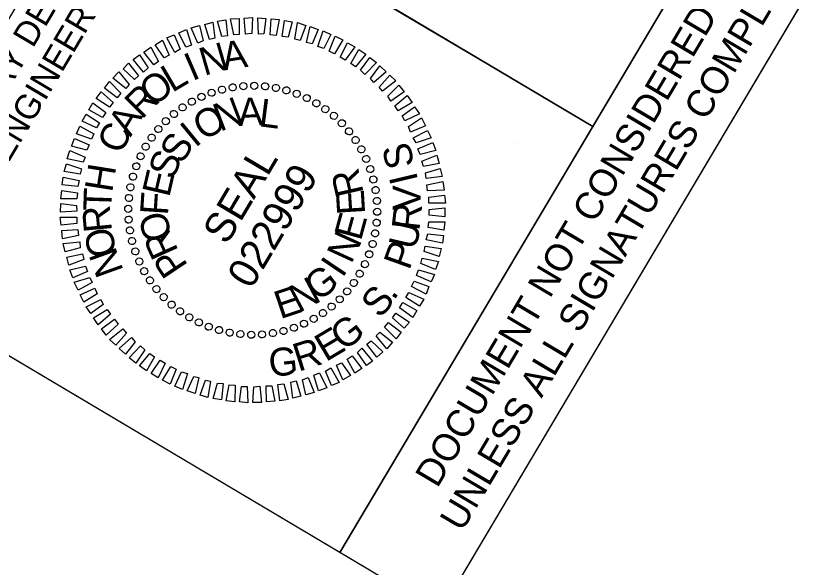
# Model space of a CAD drawing. Extents: x 2137081 to 2142019, y 404041 to 411238.
# Drawn here: x 2141049.2 to 2141211.9, y 410763.2 to 410874.6 of the extents above; entities that cross this region are included whole.
import ezdxf

# ---------------------------------------------------------------- set-up
doc = ezdxf.new("R2010")
doc.units = 0
for name, color, linetype in [('Prop Guardrail', 7, 'Continuous'), ('Sheet Clip Boundary CELL', 7, 'Continuous'), ('Sheet Plan And Profile CELL', 7, 'Continuous'), ('Sheet Sticker Exception Certification CELL', 7, 'Continuous')]:
    doc.layers.add(name, color=color, linetype=linetype)

msp = doc.modelspace()

# ---------------------------------------------------------------- linework, layer by layer
at = {"layer": 'Prop Guardrail'}
for p, q in [((2141095.05, 410860.53), (2141095.05, 410860.53)), ((2141097.3, 410860.59), (2141097.3, 410860.59)), ((2141088.66, 410859.19), (2141088.66, 410859.19)), ((2141090.77, 410859.81), (2141090.77, 410859.81)), ((2141092.92, 410860.28), (2141092.92, 410860.28)), ((2141099.45, 410860.48), (2141099.45, 410860.48)), ((2141101.6, 410860.19), (2141101.6, 410860.19)), ((2141103.75, 410859.68), (2141103.75, 410859.68)), ((2141105.87, 410858.94), (2141105.87, 410858.94)), ((2141084.67, 410857.37), (2141084.67, 410857.37)), ((2141086.65, 410858.35), (2141086.65, 410858.35)), ((2141107.83, 410858.13), (2141107.83, 410858.13)), ((2141082.81, 410856.2), (2141082.81, 410856.2)), ((2141109.78, 410857.09), (2141109.78, 410857.09)), ((2141111.63, 410855.88), (2141111.63, 410855.88)), ((2141081.01, 410854.94), (2141081.01, 410854.94)), ((2141113.37, 410854.49), (2141113.37, 410854.49)), ((2141079.42, 410853.44), (2141079.42, 410853.44)), ((2141114.95, 410853.03), (2141114.95, 410853.03)), ((2141077.89, 410851.84), (2141077.89, 410851.84)), ((2141116.42, 410851.4), (2141116.42, 410851.4)), ((2141076.53, 410850.14), (2141076.53, 410850.14)), ((2141117.71, 410849.64), (2141117.71, 410849.64)), ((2141075.32, 410848.3), (2141075.32, 410848.3)), ((2141118.92, 410847.76), (2141118.92, 410847.76)), ((2141150.48, 410848.89), (2141150.48, 410848.89)), ((2141074.28, 410846.35), (2141074.28, 410846.35)), ((2141073.44, 410844.34), (2141073.44, 410844.34)), ((2141119.86, 410845.8), (2141119.86, 410845.8)), ((2141120.75, 410843.76), (2141120.75, 410843.76)), ((2141072.77, 410842.23), (2141072.77, 410842.23)), ((2141121.36, 410841.65), (2141121.36, 410841.65)), ((2141072.21, 410840.12), (2141072.21, 410840.12)), ((2141121.83, 410839.5), (2141121.83, 410839.5)), ((2141071.96, 410837.94), (2141071.96, 410837.94)), ((2141122.06, 410837.33), (2141122.06, 410837.33)), ((2141071.83, 410835.74), (2141071.83, 410835.74)), ((2141096.94, 410835.46), (2141096.94, 410835.46)), ((2141122.15, 410835.12), (2141122.15, 410835.12)), ((2141071.92, 410833.54), (2141071.92, 410833.54)), ((2141122.01, 410832.93), (2141122.01, 410832.93)), ((2141072.14, 410831.36), (2141072.14, 410831.36)), ((2141121.68, 410830.8), (2141121.68, 410830.8)), ((2141072.62, 410829.22), (2141072.62, 410829.22)), ((2141121.21, 410828.63), (2141121.21, 410828.63)), ((2141073.23, 410827.11), (2141073.23, 410827.11)), ((2141120.45, 410826.58), (2141120.45, 410826.58)), ((2141074.03, 410825.12), (2141074.03, 410825.12)), ((2141075.05, 410823.11), (2141075.05, 410823.11)), ((2141119.61, 410824.57), (2141119.61, 410824.57)), ((2141118.57, 410822.62), (2141118.57, 410822.62)), ((2141076.18, 410821.28), (2141076.18, 410821.28)), ((2141117.36, 410820.78), (2141117.36, 410820.78)), ((2141077.46, 410819.52), (2141077.46, 410819.52)), ((2141116, 410819.08), (2141116, 410819.08)), ((2141078.94, 410817.89), (2141078.94, 410817.89)), ((2141114.56, 410817.43), (2141114.56, 410817.43)), ((2141080.61, 410816.38), (2141080.61, 410816.38)), ((2141082.26, 410815.04), (2141082.26, 410815.04)), ((2141112.88, 410815.98), (2141112.88, 410815.98)), ((2141084.11, 410813.83), (2141084.11, 410813.83)), ((2141109.31, 410813.5), (2141109.31, 410813.5)), ((2141111.17, 410814.67), (2141111.17, 410814.67)), ((2141086.05, 410812.79), (2141086.05, 410812.79)), ((2141088.1, 410811.93), (2141088.1, 410811.93)), ((2141107.33, 410812.52), (2141107.33, 410812.52)), ((2141090.14, 410811.24), (2141090.14, 410811.24)), ((2141092.29, 410810.73), (2141092.29, 410810.73)), ((2141094.44, 410810.44), (2141094.44, 410810.44)), ((2141096.68, 410810.27), (2141096.68, 410810.27)), ((2141098.84, 410810.39), (2141098.84, 410810.39)), ((2141101.06, 410810.59), (2141101.06, 410810.59)), ((2141103.2, 410811.06), (2141103.2, 410811.06)), ((2141105.32, 410811.67), (2141105.32, 410811.67))]:
    msp.add_line(p, q, dxfattribs=at)
for points in [[(2141090.71, 410870.5), (2141089.88, 410873.62), (2141091.56, 410873.9), (2141091.85, 410870.65)], [(2141093.14, 410870.87), (2141092.47, 410874.06), (2141094.25, 410874.11), (2141094.22, 410870.92)], [(2141095.53, 410870.96), (2141095.25, 410874.22), (2141096.94, 410874.32), (2141096.77, 410871.1)], [(2141098.12, 410871), (2141097.97, 410874.29), (2141099.62, 410874.13), (2141099.2, 410871.06)], [(2141100.46, 410870.83), (2141100.65, 410874.1), (2141102.3, 410873.93), (2141101.67, 410870.7)], [(2141102.93, 410870.48), (2141103.34, 410873.72), (2141104.94, 410873.47), (2141104.13, 410870.34)], [(2141083.48, 410868.33), (2141082.07, 410871.26), (2141083.62, 410871.91), (2141084.57, 410868.79)], [(2141085.85, 410869.19), (2141084.55, 410872.29), (2141086.2, 410872.72), (2141086.94, 410869.65)], [(2141088.24, 410869.87), (2141087.27, 410872.95), (2141088.92, 410873.37), (2141089.34, 410870.15)], [(2141105.43, 410869.98), (2141106.01, 410873.31), (2141107.65, 410872.74), (2141106.56, 410869.72)], [(2141107.81, 410869.27), (2141108.56, 410872.5), (2141110.2, 410871.93), (2141108.93, 410869.01)], [(2141081.22, 410867.28), (2141079.59, 410870.23), (2141081.12, 410870.84), (2141082.3, 410867.92)], [(2141110.13, 410868.47), (2141111.19, 410871.63), (2141112.76, 410870.93), (2141111.29, 410868.07)], [(2141112.38, 410867.55), (2141113.61, 410870.6), (2141115.13, 410869.82), (2141113.46, 410867.02)], [(2141079.08, 410866.22), (2141077.25, 410868.82), (2141078.73, 410869.75), (2141080.08, 410866.73)], [(2141114.58, 410866.35), (2141116.07, 410869.26), (2141117.54, 410868.39), (2141115.62, 410865.74)], [(2141076.96, 410864.8), (2141074.99, 410867.37), (2141076.38, 410868.35), (2141077.95, 410865.49)], [(2141116.74, 410865.08), (2141118.4, 410867.88), (2141119.81, 410866.92), (2141117.72, 410864.38)], [(2141074.92, 410863.33), (2141072.81, 410865.86), (2141074.07, 410866.81), (2141075.88, 410864.16)], [(2141118.7, 410863.68), (2141120.6, 410866.28), (2141121.96, 410865.24), (2141119.61, 410862.85)], [(2141073.08, 410861.8), (2141070.77, 410863.99), (2141071.9, 410865.12), (2141073.87, 410862.55)], [(2141120.74, 410862), (2141122.61, 410864.56), (2141123.89, 410863.39), (2141121.42, 410861.19)], [(2141071.33, 410860.04), (2141068.72, 410862.12), (2141069.94, 410863.38), (2141072.04, 410860.84)], [(2141122.5, 410860.26), (2141124.63, 410862.67), (2141125.83, 410861.55), (2141123.18, 410859.44)], [(2141069.6, 410858.1), (2141067.05, 410860.08), (2141068.06, 410861.4), (2141070.3, 410859.08)], [(2141124.21, 410858.43), (2141126.48, 410860.69), (2141127.56, 410859.35), (2141124.82, 410857.48)], [(2141068.03, 410856.23), (2141065.35, 410858), (2141066.36, 410859.32), (2141068.81, 410857.17)], [(2141125.62, 410856.48), (2141128.15, 410858.59), (2141129.17, 410857.17), (2141126.31, 410855.49)], [(2141066.66, 410854.13), (2141063.85, 410855.68), (2141064.7, 410857.1), (2141067.28, 410855.17)], [(2141127.12, 410854.49), (2141129.61, 410856.33), (2141130.63, 410854.91), (2141127.67, 410853.46)], [(2141065.44, 410852.06), (2141062.5, 410853.4), (2141063.34, 410854.82), (2141066.05, 410853.1)], [(2141128.4, 410852.33), (2141131.06, 410854.07), (2141131.87, 410852.48), (2141128.79, 410851.22)], [(2141064.42, 410849.76), (2141061.35, 410850.88), (2141062.02, 410852.4), (2141064.86, 410850.89)], [(2141129.38, 410850.06), (2141132.25, 410851.56), (2141132.97, 410850.02), (2141129.93, 410849.03)], [(2141063.45, 410847.53), (2141060.34, 410848.39), (2141061.01, 410849.91), (2141063.97, 410848.62)], [(2141130.27, 410847.84), (2141133.35, 410849.1), (2141133.91, 410847.48), (2141130.78, 410846.72)], [(2141062.74, 410845.16), (2141059.5, 410845.8), (2141060.03, 410847.47), (2141063.1, 410846.17)], [(2141131.13, 410845.35), (2141134.16, 410846.52), (2141134.58, 410844.88), (2141131.41, 410844.25)], [(2141062.11, 410842.73), (2141058.91, 410843.23), (2141059.36, 410844.77), (2141062.39, 410843.79)], [(2141131.84, 410843.01), (2141134.8, 410843.87), (2141135.22, 410842.22), (2141131.95, 410841.83)], [(2141061.66, 410840.21), (2141058.47, 410840.53), (2141058.7, 410842.08), (2141061.93, 410841.44)], [(2141132.13, 410840.56), (2141135.32, 410841.23), (2141135.58, 410839.5), (2141132.25, 410839.38)], [(2141061.48, 410837.75), (2141058.23, 410837.76), (2141058.42, 410839.45), (2141061.61, 410838.95)], [(2141132.54, 410838.1), (2141135.66, 410838.46), (2141135.86, 410836.83), (2141132.49, 410836.85)], [(2141061.42, 410835.28), (2141058.12, 410835.03), (2141058.22, 410836.77), (2141061.39, 410836.41)], [(2141132.56, 410835.59), (2141135.77, 410835.89), (2141135.75, 410834.1), (2141132.59, 410834.46)], [(2141061.44, 410832.76), (2141058.31, 410832.41), (2141058.11, 410834.04), (2141061.48, 410834.02)], [(2141132.49, 410833.12), (2141135.75, 410833.11), (2141135.56, 410831.42), (2141132.36, 410831.92)], [(2141061.76, 410830.36), (2141058.57, 410829.69), (2141058.39, 410831.37), (2141061.64, 410831.54)], [(2141132.32, 410830.66), (2141135.5, 410830.34), (2141135.28, 410828.79), (2141131.96, 410829.47)], [(2141062.14, 410827.86), (2141059.09, 410827.05), (2141058.67, 410828.7), (2141062.02, 410829.04)], [(2141131.78, 410828.18), (2141134.98, 410827.68), (2141134.61, 410826.09), (2141131.59, 410827.08)], [(2141062.85, 410825.52), (2141059.82, 410824.34), (2141059.4, 410825.99), (2141062.57, 410826.62)], [(2141131.15, 410825.76), (2141134.47, 410825.07), (2141133.86, 410823.45), (2141130.87, 410824.7)], [(2141063.61, 410823.08), (2141060.62, 410821.77), (2141060.06, 410823.38), (2141063.2, 410824.15)], [(2141130.44, 410823.38), (2141133.63, 410822.48), (2141132.96, 410820.96), (2141130, 410822.25)], [(2141064.51, 410820.86), (2141061.72, 410819.31), (2141060.92, 410820.9), (2141064.04, 410821.84)], [(2141129.56, 410821.11), (2141132.54, 410820.04), (2141131.95, 410818.47), (2141129.03, 410820.03)], [(2141065.58, 410818.54), (2141062.83, 410816.85), (2141062.11, 410818.38), (2141065.1, 410819.7)], [(2141128.45, 410818.85), (2141131.48, 410817.47), (2141130.63, 410816.05), (2141127.84, 410817.82)], [(2141066.77, 410816.43), (2141064.28, 410814.59), (2141063.35, 410815.96), (2141066.31, 410817.41)], [(2141127.23, 410816.79), (2141130.12, 410815.19), (2141129.28, 410813.76), (2141126.61, 410815.75)], [(2141068.27, 410814.44), (2141065.74, 410812.33), (2141064.8, 410813.7), (2141067.58, 410815.43)], [(2141069.77, 410812.44), (2141067.4, 410810.23), (2141066.42, 410811.51), (2141069.07, 410813.43)], [(2141125.86, 410814.68), (2141128.63, 410812.87), (2141127.53, 410811.6), (2141125.16, 410813.7)], [(2141124.38, 410812.77), (2141126.93, 410810.79), (2141125.91, 410809.47), (2141123.59, 410811.84)], [(2141071.48, 410810.61), (2141069.35, 410808.2), (2141068.06, 410809.37), (2141070.71, 410811.47)], [(2141122.64, 410810.83), (2141125.17, 410808.8), (2141124.04, 410807.49), (2141121.85, 410810.08)], [(2141073.24, 410808.87), (2141071.28, 410806.36), (2141070, 410807.53), (2141072.47, 410809.73)], [(2141120.9, 410809.07), (2141123.21, 410806.88), (2141121.99, 410805.8), (2141120.01, 410808.37)], [(2141075.19, 410807.24), (2141073.38, 410804.59), (2141072.01, 410805.63), (2141074.28, 410808.07)], [(2141118.97, 410807.59), (2141121.17, 410805), (2141119.91, 410804.06), (2141118.1, 410806.71)], [(2141077.15, 410805.84), (2141075.49, 410803.04), (2141074.08, 410804), (2141076.17, 410806.54)], [(2141117.02, 410806.07), (2141118.99, 410803.5), (2141117.59, 410802.52), (2141116.03, 410805.37)], [(2141079.31, 410804.56), (2141077.9, 410801.61), (2141076.44, 410802.48), (2141078.27, 410805.18)], [(2141081.51, 410803.37), (2141080.28, 410800.32), (2141078.76, 410801.1), (2141080.43, 410803.9)], [(2141112.75, 410803.59), (2141114.38, 410800.64), (2141112.85, 410800.03), (2141111.67, 410802.95)], [(2141114.89, 410804.65), (2141116.73, 410802.04), (2141115.16, 410801.17), (2141113.89, 410804.14)], [(2141083.76, 410802.45), (2141082.79, 410799.24), (2141081.22, 410799.93), (2141082.6, 410802.84)], [(2141110.41, 410802.59), (2141111.9, 410799.61), (2141110.26, 410799.01), (2141109.32, 410802.13)], [(2141086.08, 410801.65), (2141085.33, 410798.42), (2141083.69, 410798.99), (2141085.04, 410801.86)], [(2141088.46, 410800.94), (2141087.88, 410797.61), (2141086.32, 410798.13), (2141087.42, 410801.15)], [(2141090.96, 410800.44), (2141090.63, 410797.14), (2141088.95, 410797.44), (2141089.84, 410800.52)], [(2141103.26, 410800.36), (2141104.09, 410797.25), (2141102.41, 410796.97), (2141102.04, 410800.27)], [(2141105.74, 410800.99), (2141106.7, 410797.91), (2141105.06, 410797.49), (2141104.64, 410800.71)], [(2141108.12, 410801.68), (2141109.34, 410798.62), (2141107.69, 410798.2), (2141107.03, 410801.22)], [(2141093.43, 410800.09), (2141093.32, 410796.77), (2141091.59, 410796.98), (2141092.22, 410800.22)], [(2141095.86, 410799.87), (2141096, 410796.58), (2141094.27, 410796.79), (2141094.69, 410799.86)], [(2141098.36, 410799.95), (2141098.73, 410796.65), (2141096.95, 410796.6), (2141097.2, 410799.77)], [(2141100.83, 410800), (2141101.42, 410796.86), (2141099.72, 410796.76), (2141099.67, 410800)]]:
    msp.add_lwpolyline(points, close=True, dxfattribs=at)
for centre, major_axis in [((2141090.75, 410859.78), (-0.178, 0.699)), ((2141092.9, 410860.23), (-0.117, 0.712)), ((2141095.07, 410860.49), (-0.054, 0.719)), ((2141097.27, 410860.56), (0.009, 0.721)), ((2141099.46, 410860.44), (0.072, 0.718)), ((2141101.63, 410860.13), (0.134, 0.709)), ((2141086.62, 410858.33), (-0.297, 0.657)), ((2141088.65, 410859.15), (-0.239, 0.681)), ((2141103.76, 410859.63), (0.195, 0.695)), ((2141105.84, 410858.94), (0.255, 0.675)), ((2141107.86, 410858.08), (0.313, 0.65)), ((2141084.66, 410857.34), (-0.353, 0.629)), ((2141109.79, 410857.04), (0.368, 0.62)), ((2141081.04, 410854.88), (-0.457, 0.558)), ((2141082.8, 410856.19), (-0.407, 0.596)), ((2141111.62, 410855.84), (0.421, 0.586)), ((2141079.41, 410853.41), (-0.504, 0.516)), ((2141113.35, 410854.49), (0.47, 0.547)), ((2141077.91, 410851.82), (-0.547, 0.47)), ((2141114.95, 410852.99), (0.516, 0.504)), ((2141076.55, 410850.09), (-0.586, 0.421)), ((2141116.41, 410851.35), (0.558, 0.457)), ((2141117.72, 410849.6), (0.596, 0.407)), ((2141075.35, 410848.26), (-0.62, 0.368)), ((2141118.88, 410847.73), (0.629, 0.353)), ((2141074.32, 410846.33), (-0.65, 0.313)), ((2141119.87, 410845.78), (0.657, 0.297)), ((2141073.45, 410844.31), (-0.675, 0.255)), ((2141120.68, 410843.74), (0.681, 0.239)), ((2141072.77, 410842.23), (-0.695, 0.195)), ((2141121.31, 410841.64), (0.699, 0.178)), ((2141072.27, 410840.09), (-0.709, 0.134)), ((2141121.76, 410839.5), (0.712, 0.117)), ((2141071.96, 410837.92), (-0.718, 0.072)), ((2141122.02, 410837.32), (0.719, 0.054)), ((2141071.83, 410835.73), (-0.721, 0.009)), ((2141122.09, 410835.13), (0.721, -0.009)), ((2141071.9, 410833.54), (-0.719, -0.054)), ((2141121.97, 410832.94), (0.718, -0.072)), ((2141072.16, 410831.37), (-0.712, -0.117)), ((2141121.66, 410830.77), (0.709, -0.134)), ((2141072.61, 410829.22), (-0.699, -0.178)), ((2141121.16, 410828.64), (0.695, -0.195)), ((2141073.25, 410827.12), (-0.681, -0.239)), ((2141120.47, 410826.55), (0.675, -0.255)), ((2141074.06, 410825.09), (-0.657, -0.297)), ((2141119.61, 410824.54), (0.65, -0.313)), ((2141075.05, 410823.13), (-0.629, -0.353)), ((2141118.57, 410822.61), (0.62, -0.368)), ((2141076.21, 410821.27), (-0.596, -0.407)), ((2141117.37, 410820.77), (0.586, -0.421)), ((2141077.52, 410819.51), (-0.558, -0.457)), ((2141116.02, 410819.05), (0.547, -0.47)), ((2141078.98, 410817.88), (-0.516, -0.504)), ((2141114.52, 410817.45), (0.504, -0.516)), ((2141080.58, 410816.38), (-0.47, -0.547)), ((2141112.88, 410815.99), (0.457, -0.558)), ((2141082.3, 410815.02), (-0.421, -0.586)), ((2141111.13, 410814.67), (0.407, -0.596)), ((2141084.14, 410813.82), (-0.368, -0.62)), ((2141086.07, 410812.79), (-0.313, -0.65)), ((2141107.31, 410812.53), (0.297, -0.657)), ((2141109.27, 410813.52), (0.353, -0.629)), ((2141088.08, 410811.92), (-0.255, -0.675)), ((2141090.17, 410811.24), (-0.195, -0.695)), ((2141103.17, 410811.08), (0.178, -0.699)), ((2141105.27, 410811.72), (0.239, -0.681)), ((2141092.3, 410810.74), (-0.134, -0.709)), ((2141094.47, 410810.43), (-0.072, -0.718)), ((2141096.66, 410810.3), (-0.009, -0.721)), ((2141098.85, 410810.37), (0.054, -0.719)), ((2141101.03, 410810.63), (0.117, -0.712))]:
    msp.add_ellipse(centre, major_axis=major_axis, ratio=0.999708, dxfattribs=at)
at = {"layer": 'Sheet Clip Boundary CELL'}
msp.add_lwpolyline([(2140795, 409444.32), (2141473.2, 410586.96), (2141453.94, 410598.39), (2141513.05, 410697.97), (2141213, 410886.12), (2141134.78, 410754.33), (2141040.49, 410810.3), (2140938.2, 410637.97), (2140883.25, 410670.58), (2140322.04, 409725.04)], close=True, dxfattribs=at)
at = {"layer": 'Sheet Plan And Profile CELL'}
msp.add_line((2141068.89, 410909.79), (2141165.59, 410852.39), dxfattribs=at)
for points in [[(2141068.89, 410909.79), (2141119.93, 410995.78), (2141216.67, 410938.36), (2141165.63, 410852.37)], [(2141017.83, 410823.75), (2141068.89, 410909.79), (2141165.63, 410852.37), (2141114.57, 410766.33)]]:
    msp.add_lwpolyline(points, close=True, dxfattribs=at)
at = {"layer": 'Sheet Sticker Exception Certification CELL'}
for p, q in [((2141114.57, 410766.33), (2141216.67, 410938.35)), ((2141236.88, 410926.35), (2141134.78, 410754.33)), ((2141134.78, 410754.33), (2141114.57, 410766.33))]:
    msp.add_line(p, q, dxfattribs=at)

# ---------------------------------------------------------------- texts
at = {"layer": 'Prop Guardrail'}
for s, height, rotation, p in [('N', 5.65, 16.1282, (2141087.15, 410862.54)), ('A', 5.65, 8.9264, (2141091.18, 410863.64)), ('I', 5.65, 23.3294, (2141084.76, 410861.45)), ('L', 5.65, 30.5301, (2141080.68, 410859.1)), ('O', 5.65, 37.7304, (2141076.85, 410856.18)), ('R', 5.65, 44.9304, (2141074.54, 410853.65)), ('N', 5.65, 20.7859, (2141090.36, 410851.25)), ('A', 5.65, 2.0695, (2141094.08, 410852.42)), ('L', 5.65, 352.7101, (2141098.03, 410852.41)), ('O', 5.65, 30.1427, (2141087.01, 410849.34)), ('A', 5.65, 59.3296, (2141072.3, 410850.09)), ('C', 5.65, 66.5291, (2141070.54, 410846.53)), ('I', 5.65, 39.4989, (2141085.35, 410847.93)), ('S', 5.65, 58.2097, (2141082.64, 410844.53)), ('S', 5.65, 103.3787, (2141129.66, 410844.56)), ('S', 5.65, 67.5649, (2141080.88, 410841.38)), ('SEAL', 6.01, 59.3093, (2141091.73, 410828.24)), ('H', 5.65, 80.9287, (2141068.57, 410838.9)), ('022999', 6.012, 59.3093, (2141096.67, 410819.3)), ('E', 5.65, 76.9203, (2141080.09, 410837.89)), ('R', 5.65, 102.7907, (2141119.39, 410838.92)), ('I', 5.65, 103.3787, (2141130.38, 410841.45)), ('T', 5.65, 88.129, (2141068.38, 410835.23)), ('E', 5.65, 93.4333, (2141119.67, 410834.67)), ('V', 5.65, 90.1548, (2141130.86, 410835.45)), ('F', 5.65, 86.2763, (2141079.83, 410834.31)), ('R', 5.65, 95.3298, (2141068.56, 410831.22)), ('R', 5.65, 83.5428, (2141130.59, 410831.16)), ('O', 5.65, 104.9905, (2141080.76, 410829.98)), ('E', 5.65, 74.721, (2141118.79, 410829.08)), ('U', 5.65, 76.9308, (2141129.83, 410827.23)), ('O', 5.65, 102.531, (2141069.58, 410826.65)), ('R', 5.65, 114.3489, (2141082.04, 410827.23)), ('N', 5.65, 65.3656, (2141116.86, 410824.45)), ('P', 5.65, 70.3188, (2141128.56, 410823.16)), ('N', 5.65, 109.7328, (2141070.93, 410823.23)), ('P', 5.65, 123.7081, (2141084.01, 410824.26)), ('I', 5.65, 56.0105, (2141115.06, 410821.62)), ('G', 5.65, 37.2995, (2141110.14, 410816.85)), ('N', 5.65, 27.9432, (2141106.27, 410814.66)), ('E', 5.65, 18.5861, (2141102.5, 410813.4)), ('S', 5.65, 50.4828, (2141122.71, 410813.41)), ('.', 5.65, 57.0948, (2141125.47, 410817.07)), ('G', 5.65, 37.2589, (2141115.37, 410806.86)), ('E', 5.65, 30.6469, (2141111.71, 410804.74)), ('R', 5.65, 17.4229, (2141106.17, 410802.82)), ('G', 5.65, 6.2502, (2141100.48, 410801.75))]:
    msp.add_text(s, height=height, rotation=rotation, dxfattribs=at).set_placement(p)
at = {"layer": 'Sheet Plan And Profile CELL'}
for s, height, p in [('ROADWAY DESIGN', 5.0001, (2141034, 410836.71)), ('ENGINEER', 5, (2141047.62, 410844.85))]:
    msp.add_text(s, height=height, rotation=59.3093, dxfattribs=at).set_placement(p)
at = {"layer": 'Sheet Sticker Exception Certification CELL'}
for s, p in [('DOCUMENT NOT CONSIDERED FINAL', (2141134.22, 410779.17)), ('UNLESS ALL SIGNATURES COMPLETED', (2141139.2, 410770.32))]:
    msp.add_text(s, height=5.5, rotation=59.3093, dxfattribs=at).set_placement(p)

doc.saveas('drawing.dxf')
